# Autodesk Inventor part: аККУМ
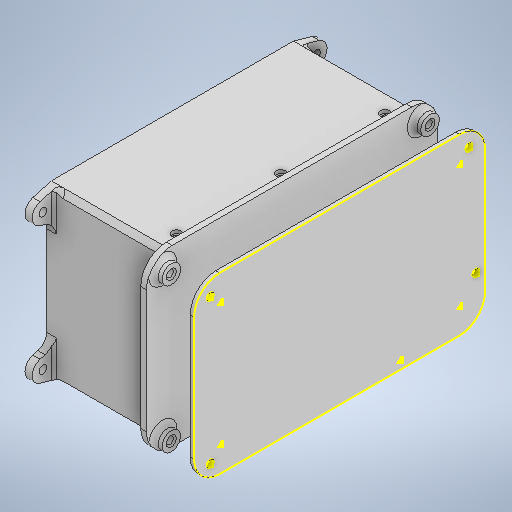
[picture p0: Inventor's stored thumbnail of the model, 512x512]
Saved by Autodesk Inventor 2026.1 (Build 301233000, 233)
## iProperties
Created: 2026-01
Part Number: аККУМ
Material: Типовые
Document SubType Name: Modeling
Designer: Yury Melnikov
Density: 1 g/cm^3
Appearance: По умолчанию
Author: Yury Melnikov
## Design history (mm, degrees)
sketch "Эскиз1"
  geometry: L1 (0, 0)-(65, 0); L2 (65, 0)-(65, 75); L3 (65, 75)-(0, 75); L4 (0, 75)-(0, 0); L5 (65, 0)-(0, 0); L6 (0, 0)-(0, -25); L7 (0, -25)-(65, -25); L8 (65, -25)-(65, 0); 1 further point
  constraints: 16 end point, 4 parallel, 2 horizontal, 2 perpendicular, 1 collinear
  dimensions: "d0" = 75 distance of L1.end L2.end; "d1" = 65 distance of L2.end L3.end; "d4" = 25 distance of L6.end L5.end
extrude "Выдавливание1" new body sketch "Эскиз1" distance "d2" = 45; taper "d3" = 0 deg
feature "Оболочка1" dims "d5" = 2.4
chamfer "Фаска1" distance "d9" = 2; stored, may be unused: second distance "d10" = 2, angle "d11" = 45 deg
sketch "Эскиз3"
  geometry: L1 (25, 63)-(25, 2) reference; L2 (23, 0)-(25, 2) reference; L3 (23, 0)-(-73, 0) reference; L4 (-75, 2)-(-73, 0) reference; L5 (-75, 2)-(-75, 63) reference; L6 (-73, 65)-(-75, 63) reference; L7 (-73, 65)-(23, 65) reference; L8 (25, 63)-(23, 65) reference; L9 (-75.4, -2.4)-(-77.4, -0.4) reference; L10 (-75.4, -2.4)-(25.4, -2.4) reference; L11 (27.4, -0.4)-(25.4, -2.4) reference; L12 (27.4, -0.4)-(27.4, 65.4) reference; L13 (25.4, 67.4)-(27.4, 65.4) reference; L14 (25.4, 67.4)-(-75.4, 67.4) reference; L15 (-77.4, 65.4)-(-75.4, 67.4) reference; L16 (-77.4, 65.4)-(-77.4, -0.4) reference; L17 (-72.917, 0.2)-(22.917, 0.2); L18 (22.917, 0.2)-(24.8, 2.083); L19 (24.8, 2.083)-(24.8, 62.917); L20 (24.8, 62.917)-(22.917, 64.8); L21 (22.917, 64.8)-(-72.917, 64.8); L22 (-72.917, 64.8)-(-74.8, 62.917); L23 (-74.8, 62.917)-(-74.8, 2.083); L24 (-74.8, 2.083)-(-72.917, 0.2); L25 (22.089, 2.2)-(-72.089, 2.2); L26 (-72.089, 2.2)-(-72.8, 2.911); L27 (-72.8, 2.911)-(-72.8, 62.089); L28 (-72.8, 62.089)-(-72.089, 62.8); L29 (-72.089, 62.8)-(22.089, 62.8); L30 (22.089, 62.8)-(22.8, 62.089); L31 (22.8, 62.089)-(22.8, 2.911); L32 (22.8, 2.911)-(22.089, 2.2); 1 further point
  constraints: 32 end point, 14 other
  dimensions: "d12" = 0.2 distance between parallel lines of L3 L17; "d13" = 2 distance between parallel lines of L17 L25
extrude "Выдавливание3" new body sketch "Эскиз3" distance "d14" = 5; taper "d15" = 0 deg
sketch "Эскиз4"
  geometry: L1 (25, 63)-(25, 2) reference; L2 (23, 0)-(25, 2) reference; L3 (23, 0)-(-73, 0) reference; L4 (-75, 2)-(-73, 0) reference; L5 (-75, 2)-(-75, 63) reference; L6 (-73, 65)-(-75, 63) reference; L7 (-73, 65)-(23, 65) reference; L8 (25, 63)-(23, 65) reference; L9 (-75.4, -2.4)-(-77.4, -0.4) reference; L10 (-75.4, -2.4)-(25.4, -2.4) reference; L11 (27.4, -0.4)-(25.4, -2.4) reference; L12 (27.4, -0.4)-(27.4, 65.4) reference; L13 (25.4, 67.4)-(27.4, 65.4) reference; L14 (25.4, 67.4)-(-75.4, 67.4) reference; L15 (-77.4, 65.4)-(-75.4, 67.4) reference; L16 (-77.4, 65.4)-(-77.4, -0.4) reference; 1 further point
extrude "Выдавливание4" join sketch "Эскиз4" distance "d16" = 2.4; taper "d17" = 0 deg
chamfer "Фаска2" distance "d18" = 2; stored, may be unused: second distance "d19" = 2, angle "d20" = 45 deg
chamfer "Фаска3" distance "d21" = 1.5; stored, may be unused: second distance "d22" = 2, angle "d23" = 45 deg
chamfer "Фаска4" distance "d24" = 0.5; stored, may be unused: second distance "d25" = 2, angle "d26" = 45 deg
sketch "Эскиз5"
  geometry: L1 (40.9, -98.317)-(40.9, -2.483) reference; L2 (45.4, -98.317)-(40.9, -98.317) reference; L3 (45.4, -2.483)-(45.4, -98.317) reference; L4 (45.4, -2.483)-(40.9, -2.483) reference; L5 (43.15, -93.817)-(43.15, -50.4); L6 (43.15, -50.4)-(43.15, -6.983); C1 r 0.75 at (43.15, -93.817); C2 r 0.75 at (43.15, -50.4); C3 r 0.75 at (43.15, -6.983); 3 further points
  constraints: 4 end point, 3 centre point, 2 collinear, 2 equal radius, 2 midpoint, 1 horizontal alignment, 1 point on line, 1 vertical
  dimensions: "d27" = 1.5 diameter of C2; "d28" = 4.5 distance from line of L2 L5.start
extrude "Выдавливание5" cut sketch "Эскиз5" distance "d29" = 75; taper "d30" = 0 deg
sketch "Эскиз8"
  geometry: L1 (-2.4, -2.4)-(98.4, -2.4) reference; L2 (-2.4, -2.4)-(72.6, -2.4); L3 (72.6, -2.4)-(72.6, 62.6); L4 (72.6, 62.6)-(-2.4, 62.6); L5 (-2.4, 62.6)-(-2.4, -2.4); L6 (74.6, -2.4)-(74.6, 62.6); L7 (72.6, -2.4)-(74.6, -2.4); L8 (72.6, 62.6)-(74.6, 62.6); L9 (74.6, 55.993)-(72.6, 55.993); L10 (72.6, 55.993)-(72.6, 64.22); L11 (72.6, 64.22)-(74.6, 64.22); L12 (74.6, 64.22)-(74.6, 55.993); 3 further points
  constraints: 22 end point, 5 parallel, 4 point on line, 3 horizontal, 2 perpendicular, 1 vertical
  dimensions: "d31" = 65 distance of L2.end L3.end; "d32" = 75 distance between parallel lines of L5 L3; "d33" = 2 distance between parallel lines of L6 L3
extrude "Выдавливание6" join sketch "Эскиз8" distance "d34" = 40; taper "d35" = 0 deg
chamfer "Фаска5" distance "d36" = 1; stored, may be unused: second distance "d37" = 2, angle "d38" = 45 deg
sketch "Эскиз9"
  geometry: L1 (0, 0)-(0, 65.8) reference; L2 (47.4, 0)-(0, 0) reference; L3 (15, 15)-(15, 50.8); C1 r 3 at (15, 15); C2 r 15 at (15, 15); C3 r 6.1 at (15, 50.8); 4 further points
  constraints: 3 centre point, 2 end point, 2 midpoint, 2 tangent, 1 coincident, 1 horizontal alignment, 1 vertical, 1 vertical alignment
  dimensions: "d39" = 6 diameter of C1; "d40" = 30 diameter of C2; "d41" = 12.2 diameter of C3
extrude "Выдавливание7" cut sketch "Эскиз9" distance "d42" = 3; taper "d43" = 0 deg
sketch "Эскиз10"
  geometry: L1 (40.4, -74)-(2.4, -74) reference; L2 (40.4, -74)-(40.4, -78) reference; L3 (2.4, -78)-(40.4, -78) reference; L4 (2.4, -98.4)-(2.4, -78) reference; L5 (45.4, -98.4)-(2.4, -98.4) reference; L6 (45.4, -2.4)-(45.4, -98.4) reference; L7 (2.4, -2.4)-(45.4, -2.4) reference; L8 (2.4, -74)-(2.4, -2.4) reference; L9 (31.65, -83.95)-(16.15, -83.95); L10 (16.15, -83.95)-(16.15, -92.45); L11 (16.15, -92.45)-(31.65, -92.45); L12 (31.65, -92.45)-(31.65, -83.95); C1 r 0.75 at (43.15, -93.817) reference; C2 r 0.75 at (43.15, -50.4) reference; C3 r 0.75 at (43.15, -6.983) reference; 5 further points
  constraints: 8 end point, 4 midpoint, 2 parallel, 1 horizontal, 1 horizontal alignment, 1 perpendicular, 1 vertical alignment
  dimensions: "d44" = 15.5 distance of L11.end L10.end; "d45" = 8.5 distance of L10.end L9.end
extrude "Выдавливание8" cut sketch "Эскиз10" distance "d46" = 3; taper "d47" = 0 deg
chamfer "Фаска6" distance "d48" = 0.7; stored, may be unused: second distance "d49" = 2, angle "d50" = 45 deg
chamfer "Фаска7" distance "d51" = 0.5; stored, may be unused: second distance "d52" = 2, angle "d53" = 45 deg
sketch "Эскиз11"
  geometry: C1 r 0.75 at (43.15, -6.983) reference; C2 r 0.75 at (43.15, -50.4) reference; C3 r 0.75 at (43.15, -93.817) reference; C4 r 2 at (43.15, -6.983); C5 r 2 at (43.15, -50.4); C6 r 2 at (43.15, -93.817); 1 further point
  constraints: 3 centre point, 2 equal radius
  dimensions: "d54" = 4 diameter of C4
extrude "Выдавливание9" cut sketch "Эскиз11" distance "d55" = 1.4; taper "d56" = 0 deg
chamfer "Фаска8" distance "d57" = 0.5; stored, may be unused: second distance "d58" = 2, angle "d59" = 45 deg
node "РабПлоскость2"
mirror "Зеркальное отражение1"
node "РабПлоскость3"
sketch "Эскиз12"
  geometry: L1 (2, 61)-(2, 0) reference; L2 (2, 0)-(2, 61) reference; L3 (2, 9.6)-(2, 15.6) reference; L4 (2, 42.3)-(2, 54.5) reference; L5 (2, 49)-(-4.5, 49); L6 (-4.5, 49)-(-4.5, 42); L7 (-4.5, 42)-(-2.5, 42); L8 (-2.5, 42)-(-2.5, 47); L9 (-2.5, 47)-(2, 47); L10 (-2.5, 47)-(-2.5, 49); L11 (2, 30.5)-(16.292, 30.5); L12 (2, 18.7)-(2, 6.5); L13 (2, 12)-(-4.5, 12); L14 (-4.5, 12)-(-4.5, 19); L15 (-4.5, 19)-(-2.5, 19); L16 (-2.5, 19)-(-2.5, 14); L17 (-2.5, 14)-(2, 14); L18 (-2.5, 14)-(-2.5, 12); 6 further points
  constraints: 28 end point, 9 symmetric about line, 8 point on line, 3 horizontal, 3 perpendicular, 2 midpoint, 1 vertical
  dimensions: "d62" = 5 distance of L7.end L8.end; "d63" = 2 distance of L6.end L7.end; "d64" = 4.5 distance of L8.end L9.end; "d65" = 33 distance from line of L17 point (-0.25, 47)
extrude "Выдавливание10" join sketch "Эскиз12" distance "d66" = 6; taper "d67" = 0 deg
sketch "Эскиз13"
  geometry: L1 (37, 16.4)-(37, 21.4) reference; L2 (37, 21.4)-(31, 21.4) reference; L3 (31, 16.4)-(31, 21.4) reference; L4 (37, 16.4)-(31, 16.4) reference; L5 (37, 44.4)-(37, 49.4) reference; L6 (37, 49.4)-(31, 49.4) reference; L7 (31, 44.4)-(31, 49.4) reference; L8 (37, 44.4)-(31, 44.4) reference; L9 (27.35, 16.65)-(40.65, 16.65); L10 (40.65, 16.65)-(40.65, 49.15); L11 (40.65, 49.15)-(27.35, 49.15); L12 (27.35, 49.15)-(27.35, 16.65); L13 (31, 21.4)-(31, 44.4); C1 r 1.65 at (30.35, 41.15); C2 r 1.65 at (30.35, 36.15); C3 r 1.65 at (30.35, 31.15); C4 r 1.65 at (30.35, 26.15); C5 r 2.1 at (35.65, 41.65); 5 further points
  constraints: 10 end point, 5 centre point, 4 midpoint, 2 parallel, 2 vertical, 1 horizontal, 1 horizontal alignment, 1 perpendicular, 1 vertical alignment, 6 other
  dimensions: "d68" = 32.5 distance of L11.end L9.start; "d69" = 13.3 distance of L9.start L9.end; "d70" = 3 horizontal distance of C1.centre L11.end; "d71" = 8 vertical distance of L11.end C1.centre; "d72" = 3.3 diameter of C1; "d75" = 5 distance of C1.centre C2.centre; "d80" = 4.2 diameter of C5; "d81" = 7.5 vertical distance of L10.end C5.centre; "d82" = 5 distance from line of L10 C5.centre
extrude "Выдавливание11" cut sketch "Эскиз13" distance "d83" = 6; taper "d84" = 0 deg
chamfer "Фаска9" distance "d85" = 0.5; stored, may be unused: second distance "d86" = 2, angle "d87" = 45 deg
chamfer "Фаска10" distance "d88" = 3; stored, may be unused: second distance "d89" = 2, angle "d90" = 45 deg
sketch "Эскиз15"
  geometry: L1 (-77.4, 67.4)-(27.4, 67.4); L2 (27.4, 67.4)-(27.4, -2.4); L3 (27.4, -2.4)-(-77.4, -2.4); L4 (-77.4, -2.4)-(-77.4, 67.4); L5 (25.4, 67.4)-(-75.4, 67.4) reference; L6 (-77.4, 65.4)-(-77.4, -0.4) reference; L7 (-75.4, -2.4)-(25.4, -2.4) reference; L8 (27.4, -0.4)-(27.4, 65.4) reference; 1 further point
  constraints: 8 end point, 4 collinear, 2 parallel, 1 horizontal, 1 perpendicular
  dimensions: "d99" = 104.8 distance of L1.start L1.end (derived); "d100" = 69.8 distance of L1.end L2.end (derived)
sketch "Эскиз16"
  geometry: L1 (-2.4, -2)-(47.4, -2); L2 (47.4, -2)-(47.4, 67.8); L3 (47.4, 67.8)-(-2.4, 67.8); L4 (-2.4, 67.8)-(-2.4, -2); L5 (47.4, 67.8)-(0, 67.8) reference; L6 (47.4, 0)-(47.4, 65.8) reference; L7 (-2.4, 64.972)-(-2.4, 0.828) reference; L8 (0, -2)-(47.4, -2) reference; 3 further points
  constraints: 8 end point, 4 collinear, 2 parallel, 1 horizontal, 1 perpendicular
  dimensions: "d101" = 49.8 distance of L2.end L3.end (derived)
sketch "Эскиз17"
  geometry: L1 (15.4, 55.4)-(15.4, 9.6); L2 (15.4, 9.6)-(-65.4, 32.5); L3 (27.4, -0.4)-(27.4, 65.4) reference; L4 (-74.572, 65.4)-(24.572, 65.4) reference; L5 (25.4, 64.572)-(25.4, 0.428) reference; L6 (24.572, -0.4)-(-74.572, -0.4) reference; L7 (-75.4, 0.428)-(-75.4, 64.572) reference; C1 r 2 at (-65.4, 32.5); C2 r 2 at (15.4, 55.4); C3 r 2 at (15.4, 9.6); C4 r 10 at (15.4, 55.4); C5 r 10 at (15.4, 9.6); C6 r 10 at (-65.4, 32.5); 3 further points
  constraints: 6 centre point, 4 end point, 4 tangent, 3 coincident, 3 equal radius, 2 horizontal alignment, 2 midpoint, 1 vertical, 1 vertical alignment
  dimensions: "d102" = 4 diameter of C1; "d103" = 8 distance edge to line of C1 L7
extrude "Выдавливание13" cut sketch "Эскиз17" distance "d104" = 10; taper "d105" = 0 deg
sketch "Эскиз20"
  geometry: L1 (-25.4, 67.4)-(75.4, 67.4) reference; L2 (-27.4, -2.4)-(-27.4, 67.4) reference; L3 (-47.022, 65.4)-(-10.668, 65.4); L4 (-58.591, -0.4)-(13.104, -0.4); L5 (77.4, 65.4)-(77.4, -0.4) reference; L6 (75.4, 67.4)-(83.117, 65.232); L7 (83.117, 56.568)-(77.4, 54.962); L8 (83.117, 65.232)-(77.4, 66.838); L9 (25, 67.4)-(25, 80.723); L10 (77.4, 32.5)-(86.793, 32.5); L11 (-25.4, 67.4)-(-33.117, 65.232); L12 (-33.117, 56.568)-(-27.4, 54.962); L13 (-47.022, -0.4)-(-10.668, -0.4); L14 (-33.117, 8.432)-(-27.4, 10.038); L15 (-25.4, -2.4)-(-33.117, -0.232); L16 (-25.4, -2.4)-(75.4, -2.4); L17 (83.117, 8.432)-(77.4, 10.038); L18 (83.117, -0.232)-(77.4, -1.838); L19 (75.4, -2.4)-(83.117, -0.232); L20 (-27.4, 65.4)-(-25.4, 67.4) reference; L21 (-27.4, -0.4)-(-27.4, 65.4) reference; L22 (-25.4, -2.4)-(-27.4, -0.4) reference; L23 (75.4, -2.4)-(-25.4, -2.4) reference; L24 (77.4, -0.4)-(75.4, -2.4) reference; L25 (77.4, 65.4)-(77.4, -0.4) reference; L26 (75.4, 67.4)-(77.4, 65.4) reference; L27 (-25.4, 67.4)-(75.4, 67.4) reference; C1 r 1.65 at (-31.9, 60.9); C2 r 4.5 at (-31.9, 60.9); C3 r 1.65 at (81.9, 60.9); C4 r 1.65 at (-31.9, 4.1); C5 r 4.5 at (-31.9, 4.1); C6 r 1.65 at (81.9, 4.1); C7 r 4.5 at (81.9, 4.1); C8 r 4.5 at (-31.9, 4.1); C9 r 1.65 at (-31.9, 4.1); C10 r 1.65 at (81.9, 4.1); A1 r 4.5 centre (81.9, 60.9) between (83.117, 56.568) and (83.117, 65.232); A2 r 5.938 centre (77.4, 60.9) between (77.4, 66.838) and (77.4, 54.962); A3 r 4.5 centre (81.9, 4.1) between (83.117, 8.432) and (83.117, -0.232); A4 r 5.938 centre (77.4, 4.1) between (77.4, -1.838) and (77.4, 10.038); 21 further points
  constraints: 32 end point, 20 symmetric about line, 14 centre point, 10 point on circle, 8 point on line, 6 coincident, 6 tangent, 4 horizontal, 2 midpoint, 2 vertical, 1 collinear, 17 other
  dimensions: "d122" = 3.3 diameter of C1; "d123" = 9 diameter of C2; "d126" = 113.8 distance of C1.centre C3.centre (derived); "d129" = 56.8 distance of C1.centre C4.centre (derived)
extrude "Выдавливание16" join sketch "Эскиз20" distance "d132" = 3; taper "d133" = 0 deg
fillet "Сопряжение1" dims "d134" = 5
node "РабПлоскость5"
chamfer "Фаска12" distance "d135" = 1; stored, may be unused: second distance "d136" = 2, angle "d137" = 45 deg
sketch "Эскиз21"
  geometry: L1 (-31.9, 60.9)-(81.9, 60.9); L2 (81.9, 60.9)-(81.9, 4.1); L3 (81.9, 4.1)-(-31.9, 4.1); L4 (-31.9, 4.1)-(-31.9, 60.9); C1 r 1.65 at (-31.9, 60.9) reference; C2 r 1.65 at (81.9, 4.1) reference; 1 further point
  constraints: 8 end point, 2 parallel, 1 horizontal, 1 perpendicular
  dimensions: "d138" = 56.8 distance of L1.end L2.end (derived); "d139" = 113.8 distance of L1.start L1.end (derived)
sketch "Эскиз22"
  geometry: L1 (-74.911, 68.773)-(24.911, 68.773); L2 (-85.594, 58.09)-(-85.594, 6.909); L3 (-74.911, -3.774)-(24.911, -3.774); L4 (35.594, 6.909)-(35.594, 58.09); L5 (-75.4, 0.428)-(-75.4, 64.572) reference; L6 (-74.572, -0.4)-(-75.4, 0.428) reference; L7 (24.572, -0.4)-(-74.572, -0.4) reference; L8 (25.4, 0.428)-(24.572, -0.4) reference; L9 (25.4, 64.572)-(25.4, 0.428) reference; L10 (24.572, 65.4)-(25.4, 64.572) reference; L11 (-74.572, 65.4)-(24.572, 65.4) reference; L12 (-75.4, 64.572)-(-74.572, 65.4) reference; L13 (24.572, 65.4)-(25.4, 65.4); L14 (25.4, 65.4)-(25.4, 64.572); L15 (-74.572, 65.4)-(-75.4, 65.4); L16 (-75.4, 65.4)-(-75.4, 64.572); L17 (-75.4, 0.428)-(-77.4, -0.4) reference; L18 (-75.4, 0.428)-(-75.4, -0.4); L19 (-75.4, -0.4)-(-74.572, -0.4); C1 r 1.5 at (-78.848, 62.155); C2 r 1.5 at (28.848, 62.155); C3 r 1.5 at (-78.848, 1.957); C4 r 1.5 at (31.738, 15.419); C5 r 66.772 at (-25, 32.5); C6 r 2 at (15.4, 55.4) reference; C7 r 2 at (15.4, 9.6) reference; C8 r 2 at (-65.4, 32.5) reference; A1 r 10.683 centre (-74.911, 58.09) between (-74.911, 68.773) and (-85.594, 58.09); A2 r 10.683 centre (-74.911, 6.909) between (-85.594, 6.909) and (-74.911, -3.774); A3 r 10.683 centre (24.911, 6.909) between (24.911, -3.774) and (35.594, 6.909); A4 r 10.683 centre (24.911, 58.09) between (35.594, 58.09) and (24.911, 68.773); A5 r 60.188 centre (-25, 32.5) between (25.4, 65.4) and (-75.4, 65.4); 5 further points
  constraints: 20 end point, 11 point on circle, 11 tangent, 10 centre point, 4 coincident, 4 perpendicular, 3 equal radius, 3 horizontal, 3 vertical, 2 point on line, 1 concentric, 1 horizontal alignment, 1 vertical alignment
  dimensions: "d140" = 60.198 distance of point (-78.848, 1.957) point (-78.848, 62.155); "d141" = 107.696 distance of point (28.848, 62.155) point (-78.848, 62.155); "d142" = 110.586 horizontal distance of point (31.738, 15.419) point (-78.848, 62.155); "d143" = 46.736 vertical distance of point (-78.848, 62.155) point (31.738, 15.419); "d144" = 3 diameter of C1; "d145" = 3.937 horizontal distance of C1.centre A1.centre; "d146" = -4.064 vertical distance of C1.centre A1.centre; "d147" = 10.683 radius of A1; "d148" = 51.181 distance of L2.start L2.end; "d149" = 10.683 radius of A2; "d150" = 99.822 distance of L3.start L3.end; "d151" = 10.683 radius of A3; "d152" = 10.683 radius of A4
extrude "Выдавливание17" new body sketch "Эскиз22" distance "d153" = 1.6; taper "d154" = 0 deg
sketch "Эскиз23"
  geometry: L1 (85.594, 58.09)-(85.594, 6.909) reference; L2 (-24.911, 68.773)-(74.911, 68.773) reference; L3 (-35.594, 6.909)-(-35.594, 58.09) reference; L4 (74.911, -3.774)-(-24.911, -3.774) reference; C1 r 1.5 at (-31.738, 15.419) reference; C2 r 1.5 at (78.848, 1.957) reference; C3 r 1.5 at (-28.848, 62.155) reference; C4 r 1.5 at (78.848, 62.155) reference; C5 r 2 at (-15.4, 55.4) reference; C6 r 2 at (65.4, 32.5) reference; C7 r 2 at (-15.4, 9.6) reference; A1 r 10.683 centre (74.911, 58.09) between (85.594, 58.09) and (74.911, 68.773) reference; A2 r 10.683 centre (-24.911, 58.09) between (-24.911, 68.773) and (-35.594, 58.09) reference; A3 r 10.683 centre (-24.911, 6.909) between (-35.594, 6.909) and (-24.911, -3.774) reference; A4 r 10.683 centre (74.911, 6.909) between (74.911, -3.774) and (85.594, 6.909) reference; 1 further point
extrude "Выдавливание18" join sketch "Эскиз23" stored distance "d155" = 1.6; taper "d156" = 0 deg
sketch "Эскиз24"
  geometry: C1 r 1.5 at (31.738, 15.419) reference; C2 r 1.5 at (28.848, 62.155) reference; C3 r 1.5 at (-78.848, 1.957) reference; C4 r 1.5 at (-78.848, 62.155) reference; C5 r 1.5 at (-78.848, 1.957); C6 r 1.5 at (-78.848, 62.155); C7 r 1.5 at (28.848, 62.155); C8 r 1.5 at (31.738, 15.419); 1 further point
  constraints: 4 centre point, 3 equal radius
  dimensions: "d157" = 3 diameter of C8
extrude "Выдавливание19" cut sketch "Эскиз24" distance "d158" = 10; taper "d159" = 0 deg
sketch "Эскиз25"
  geometry: L1 (-35.594, 58.09)-(-35.594, 6.909) reference; L2 (-24.911, -3.774)-(74.911, -3.774) reference; L3 (85.594, 6.909)-(85.594, 58.09) reference; L4 (74.911, 68.773)-(-24.911, 68.773) reference; L5 (-24.8, 2.083)-(-24.8, 62.917) reference; L6 (-24.8, 62.917)-(-22.917, 64.8) reference; L7 (-22.917, 64.8)-(72.917, 64.8) reference; L8 (72.917, 64.8)-(74.8, 62.917) reference; L9 (74.8, 62.917)-(74.8, 2.083) reference; L10 (74.8, 2.083)-(72.917, 0.2) reference; L11 (72.917, 0.2)-(-22.917, 0.2) reference; L12 (-22.917, 0.2)-(-24.8, 2.083) reference; L13 (-35.594, 58.09)-(-35.594, 6.909) reference; L14 (-35.594, 58.09)-(-35.594, 6.909) reference; L15 (74.911, 68.773)-(-24.911, 68.773) reference; L16 (85.594, 6.909)-(85.594, 58.09) reference; L17 (-24.911, -3.774)-(74.911, -3.774) reference; C1 r 3.856 at (-31.738, 15.419); C2 r 3.856 at (-28.848, 62.155); C3 r 3.856 at (78.848, 62.155); C4 r 3.856 at (78.848, 1.957); C5 r 1.5 at (78.848, 62.155) reference; C6 r 1.5 at (78.848, 1.957) reference; C7 r 1.5 at (-28.848, 62.155) reference; C8 r 1.5 at (-31.738, 15.419) reference; C9 r 2 at (-15.4, 55.4) reference; C10 r 2 at (-15.4, 9.6) reference; C11 r 2 at (65.4, 32.5) reference; A1 r 10.683 centre (-24.911, 58.09) between (-24.911, 68.773) and (-35.594, 58.09) reference; A2 r 10.683 centre (-24.911, 6.909) between (-35.594, 6.909) and (-24.911, -3.774) reference; A3 r 10.683 centre (74.911, 6.909) between (74.911, -3.774) and (85.594, 6.909) reference; A4 r 10.683 centre (74.911, 58.09) between (85.594, 58.09) and (74.911, 68.773) reference; A5 r 10.683 centre (-24.911, 58.09) between (-24.911, 68.773) and (-35.594, 58.09) reference; A6 r 10.683 centre (74.911, 58.09) between (85.594, 58.09) and (74.911, 68.773) reference; A7 r 10.683 centre (74.911, 6.909) between (74.911, -3.774) and (85.594, 6.909) reference; A8 r 10.683 centre (-24.911, 6.909) between (-35.594, 6.909) and (-24.911, -3.774) reference; 1 further point
  constraints: 4 centre point, 3 equal radius, 1 tangent
extrude "Выдавливание20" join sketch "Эскиз25" distance "d161" = 6; taper "d162" = 0 deg
fillet "Сопряжение2" dims "d163" = 2
chamfer "Фаска13" distance "d164" = 0.6; stored, may be unused: second distance "d165" = 2, angle "d166" = 45 deg
sketch "Эскиз26"
  geometry: L1 (-74.911, 68.773)-(24.911, 68.773) reference; L2 (-85.594, 6.909)-(-85.594, 58.09) reference; L3 (24.911, -3.774)-(-74.911, -3.774) reference; L4 (35.594, 11.011)-(35.594, 6.909) reference; L5 (35.594, 58.09)-(35.594, 19.826) reference; C1 r 2 at (-65.4, 32.5) reference; C2 r 2 at (15.4, 9.6) reference; C3 r 2 at (15.4, 55.4) reference; A1 r 5.856 centre (28.848, 62.155) between (28.876, 68.01) and (34.7, 62.368) reference; A2 r 10.683 centre (24.911, 58.09) between (28.876, 68.01) and (24.911, 68.773) reference; A3 r 10.683 centre (-74.911, 58.09) between (-74.911, 68.773) and (-78.876, 68.01) reference; A4 r 5.856 centre (-78.848, 62.155) between (-84.7, 62.368) and (-78.876, 68.01) reference; A5 r 10.683 centre (-74.911, 58.09) between (-84.7, 62.368) and (-85.594, 58.09) reference; A6 r 10.683 centre (-74.911, 6.909) between (-85.594, 6.909) and (-84.672, 2.568) reference; A7 r 5.856 centre (-78.848, 1.957) between (-76.938, -3.579) and (-84.672, 2.568) reference; A8 r 10.683 centre (-74.911, 6.909) between (-76.938, -3.579) and (-74.911, -3.774) reference; A9 r 10.683 centre (24.911, 6.909) between (24.911, -3.774) and (35.594, 6.909) reference; A10 r 5.856 centre (31.738, 15.419) between (35.594, 19.826) and (35.594, 11.011) reference; A11 r 10.683 centre (24.911, 58.09) between (35.594, 58.09) and (34.7, 62.368) reference; 1 further point
extrude "Выдавливание21" join sketch "Эскиз26" stored distance "d167" = 6; taper "d168" = 0 deg
sketch "Эскиз28"
  geometry: C1 r 0.75 at (-2.25, 4.5) reference; C2 r 0.75 at (-2.25, 47.917) reference; C3 r 0.75 at (-2.25, 91.334) reference; 1 further point
sketch "Эскиз29"
  geometry: L1 (-19.167, 2.2)-(-17.667, 2.2) reference; L2 (24.25, 2.2)-(25.75, 2.2) reference; L3 (67.667, 2.2)-(69.167, 2.2) reference; L4 (69.167, 62.8)-(67.667, 62.8) reference; L5 (25.75, 62.8)-(24.25, 62.8) reference; L6 (-17.667, 62.8)-(-19.167, 62.8) reference; L7 (-20.667, 2.2)-(-16.167, 2.2); L8 (-16.167, 2.2)-(-16.167, 6.2); L9 (-16.167, 6.2)-(-20.667, 6.2); L10 (-20.667, 6.2)-(-20.667, 2.2); L11 (27.25, 2.2)-(27.25, 6.2); L12 (22.75, 2.2)-(27.25, 2.2); L13 (22.75, 6.2)-(22.75, 2.2); L14 (27.25, 6.2)-(22.75, 6.2); L15 (70.667, 2.2)-(70.667, 6.2); L16 (66.167, 2.2)-(70.667, 2.2); L17 (66.167, 6.2)-(66.167, 2.2); L18 (70.667, 6.2)-(66.167, 6.2); L19 (71.3, 61.3)-(71.3, 3.7) reference; L20 (71.3, 32.5)-(55.911, 32.5); L21 (67.667, 62.8)-(69.167, 62.8); L22 (66.167, 58.8)-(66.167, 62.8); L23 (66.167, 62.8)-(70.667, 62.8); L24 (70.667, 62.8)-(70.667, 58.8); L25 (70.667, 58.8)-(66.167, 58.8); L26 (-16.167, 62.8)-(-16.167, 58.8); L27 (-20.667, 62.8)-(-16.167, 62.8); L28 (-16.167, 58.8)-(-20.667, 58.8); L29 (-20.667, 58.8)-(-20.667, 62.8); L30 (-19.167, 62.8)-(-17.667, 62.8); L31 (24.25, 62.8)-(25.75, 62.8); L32 (27.25, 62.8)-(27.25, 58.8); L33 (22.75, 58.8)-(22.75, 62.8); L34 (22.75, 62.8)-(27.25, 62.8); L35 (27.25, 58.8)-(22.75, 58.8); 30 further points
  constraints: 56 end point, 21 symmetric about line, 8 horizontal alignment, 6 parallel, 5 midpoint, 4 collinear, 3 horizontal, 2 vertical alignment, 1 perpendicular, 6 other
  dimensions: "d174" = 43.41716 distance of L7.end L11.start (derived); "d179" = 1.5 distance from line of L10 L1.start; "d180" = 4 distance of L9.end L7.start
extrude "Выдавливание23" join sketch "Эскиз29" stored distance "d181" = 10; taper "d182" = 0 deg
extrude "Выдавливание24" cut sketch "Эскиз28" stored distance "d183" = 10; taper "d184" = 0 deg
fillet "Сопряжение3" dims "d185" = 2
chamfer "Фаска14" distance "d186" = 0.6; stored, may be unused: second distance "d187" = 2, angle "d188" = 45 deg
sketch "Эскиз31"
  geometry: L1 (-85.594, 58.09)-(-85.594, 6.909) reference; L2 (-74.911, -3.774)-(24.911, -3.774) reference; L3 (35.594, 6.909)-(35.594, 58.09) reference; L4 (24.911, 68.773)-(-74.911, 68.773) reference; C1 r 1.5 at (31.738, 15.419) reference; C2 r 1.5 at (-78.848, 1.957) reference; C3 r 1.5 at (28.848, 62.155) reference; C4 r 1.5 at (-78.848, 62.155) reference; A1 r 10.683 centre (-74.911, 6.909) between (-85.594, 6.909) and (-74.911, -3.774) reference; A2 r 10.683 centre (24.911, 6.909) between (24.911, -3.774) and (35.594, 6.909) reference; A3 r 10.683 centre (24.911, 58.09) between (35.594, 58.09) and (24.911, 68.773) reference; A4 r 10.683 centre (-74.911, 58.09) between (-74.911, 68.773) and (-85.594, 58.09) reference; 1 further point
  node "Спроецированная петля19"
sketch "Эскиз32"
  geometry: 1 further point
feature "ݽ耀ݿ耀ށ耀ރ耀ޅ耀އ耀މ耀ދ耀" dims "d0" = 75, "d1" = 65, "d2" = 45, "d3" = 0, "d4" = 25, "d5" = 2.4, "d9" = 2, "d10" = 2, "d11" = 45 deg, "d12" = 0.2, "d13" = 2, "d14" = 5, "d15" = 0, "d16" = 2.4, "d17" = 0, "d18" = 2, "d19" = 2, "d20" = 45 deg, "d21" = 1.5, "d22" = 2, "d23" = 45 deg, "d24" = 0.5, "d25" = 2, "d26" = 45 deg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
feature "ย耀ฤ耀ฦ耀ศ耀ส耀ฬ耀ฮ耀ะ耀" dims "d0" = 75, "d1" = 65, "d2" = 45, "d3" = 0, "d4" = 25, "d5" = 2.4, "d9" = 2, "d10" = 2, "d11" = 45 deg, "d12" = 0.2, "d13" = 2, "d14" = 5, "d15" = 0, "d16" = 2.4, "d17" = 0, "d18" = 2, "d19" = 2, "d20" = 45 deg, "d21" = 1.5, "d22" = 2, "d23" = 45 deg, "d24" = 0.5, "d25" = 2, "d26" = 45 deg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
node "Твердое тело1"
node "Спроецированная петля2"
node "Твердое тело2"
node "Спроецированная петля3"
node "Спроецированная петля4"
node "Спроецированная петля5"
node "Спроецированная петля6"
node "Спроецированная петля7"
node "Спроецированная петля8"
node "Эскиз — прямоугольный массив1" dims "d75" = 5, "d78" = 10
node "Эскиз — прямоугольный массив3" dims "d126" = 113.8 (derived), "d129" = 56.8 (derived)
node "Спроецированная петля11"
node "Спроецированная петля12"
node "Плаьа"
node "Спроецированная петля13"
node "Спроецированная петля14"
node "Спроецированная петля15"
node "Эскиз — прямоугольный массив4" dims "d174" = 43.41716 (derived), "d177" = 10
node "Спроецированная петля17"
